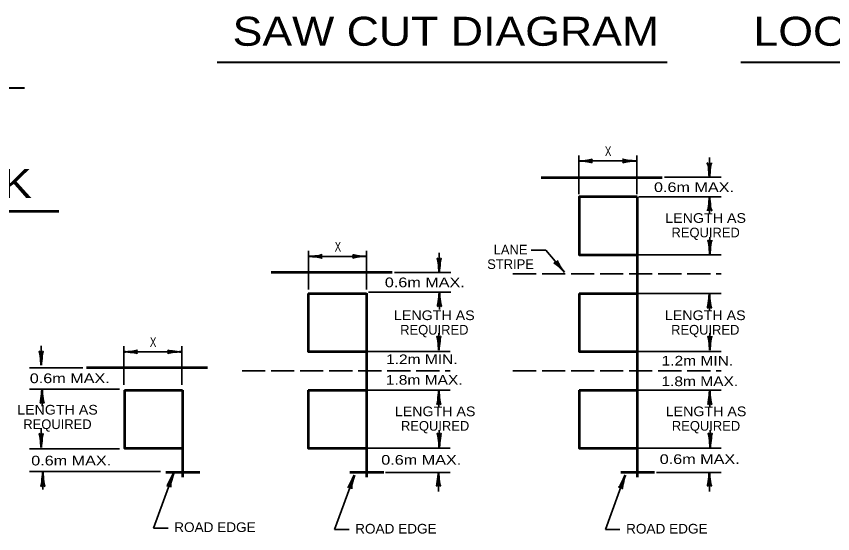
# Model space of a CAD drawing. Extents: x -90 to 623, y -379 to 75.
# Drawn here: x 208.1 to 376.8, y -182.3 to -75.3 of the extents above; entities that cross this region are included whole.
import ezdxf
from ezdxf.enums import TextEntityAlignment as Align

# ---------------------------------------------------------------- set-up
doc = ezdxf.new("R2010")
doc.units = 0
doc.header["$LTSCALE"] = 0.8
doc.linetypes.add('LONG_DASHED', pattern=[7.5, 6, -1.5])
doc.layers.add('1', color=7, linetype='Continuous', lineweight=35)

msp = doc.modelspace()

# ---------------------------------------------------------------- linework, layer by layer
at = {"layer": '1', "lineweight": 40}
for p, q in [((249.5781, -84.8174), (342.6167, -84.8174)), ((357.8467, -84.8174), (443.6682, -84.8174)), ((128.1151, -90.0752), (209.7699, -90.0752))]:
    msp.add_line(p, q, dxfattribs=at)
at = {"layer": '1'}
for p, q in [((324.3488, -112.0774), (324.3488, -104.0774)), ((336.3488, -112.0774), (336.3488, -104.0774)), ((351.3414, -108.4852), (351.3414, -104.4852)), ((324.2692, -105.2347), (336.2847, -105.2347)), ((342.092, -108.5765), (353.7611, -108.5765)), ((336.7611, -112.6343), (353.7611, -112.6343)), ((351.3812, -116.186), (351.3812, -112.686)), ((351.4209, -124.4781), (351.4209, -120.9781)), ((268.4928, -131.8101), (268.4928, -123.8101)), ((280.4928, -131.8101), (280.4928, -123.8101)), ((295.4853, -128.2178), (295.4853, -124.2178)), ((336.7611, -124.6343), (353.7611, -124.6343)), ((268.4132, -124.9674), (280.4287, -124.9674)), ((286.2359, -128.3092), (297.905, -128.3092)), ((280.905, -132.367), (297.905, -132.367)), ((295.5251, -135.9187), (295.5251, -132.4187)), ((336.7611, -132.6343), (353.7611, -132.6343)), ((351.3414, -136.2764), (351.3414, -132.7764)), ((295.4209, -144.3696), (295.4209, -140.8696)), ((351.4209, -144.3696), (351.4209, -140.8696)), ((213.2128, -147.4731), (213.2128, -143.4731)), ((230.221, -144.7001), (242.2365, -144.7001)), ((230.3006, -151.5427), (230.3006, -143.5427)), ((242.3006, -151.5427), (242.3006, -143.5427)), ((280.7611, -144.6343), (297.7611, -144.6343)), ((336.7611, -144.6343), (353.7611, -144.6343)), ((221.8063, -147.9942), (210.8156, -147.9942)), ((229.4447, -152.45), (210.8156, -152.45)), ((213.4117, -155.9697), (213.4117, -152.4697)), ((280.7611, -152.6343), (297.7611, -152.6343)), ((295.4209, -156.2476), (295.4209, -152.7476)), ((336.7611, -152.6343), (353.7611, -152.6343)), ((351.4209, -156.2476), (351.4209, -152.7476)), ((213.2128, -164.5004), (213.2128, -160.5004)), ((295.5005, -164.4203), (295.5005, -160.9203)), ((351.5005, -164.4203), (351.5005, -160.9203)), ((229.4447, -164.7682), (210.8156, -164.7682)), ((280.7611, -164.6343), (297.7611, -164.6343)), ((336.7611, -164.6343), (353.7611, -164.6343)), ((237.8789, -169.4774), (210.8156, -169.4774)), ((213.5708, -173.1562), (213.5708, -169.6562)), ((240.5595, -169.8673), (236.4582, -181.1357)), ((277.9561, -170.1856), (273.8548, -181.4539)), ((284.421, -169.6232), (297.7611, -169.6232)), ((295.3413, -173.6157), (295.3413, -169.6157)), ((333.9561, -170.1856), (329.8548, -181.4539)), ((340.421, -169.6232), (353.7611, -169.6232)), ((351.3413, -173.6157), (351.3413, -169.6157)), ((236.4582, -181.1357), (239.4582, -181.1357)), ((273.8548, -181.4539), (276.8548, -181.4539)), ((329.8548, -181.4539), (332.8548, -181.4539))]:
    msp.add_line(p, q, dxfattribs=at)
at = {"layer": '1', "lineweight": 53}
for p, q in [((316.5513, -108.6561), (341.5513, -108.6561)), ((336.4429, -112.6152), (336.4429, -170.6152)), ((0.8544, -115.6087), (216.8702, -115.6087)), ((260.7747, -128.2296), (285.7747, -128.2296)), ((268.4429, -132.6152), (280.4429, -132.6152)), ((280.4429, -132.5694), (280.4429, -170.6152)), ((280.4429, -132.649), (280.4429, -170.6152)), ((324.4429, -132.6152), (336.4429, -132.6152)), ((222.5826, -147.9622), (247.5826, -147.9622)), ((230.4429, -152.6152), (242.4429, -152.6152)), ((242.4429, -152.6152), (242.4429, -170.6152)), ((242.4429, -152.6292), (242.4429, -170.6152)), ((268.4429, -152.6152), (280.4429, -152.6152)), ((324.4429, -152.6152), (336.4429, -152.6152)), ((239.0214, -169.5842), (246.0214, -169.5842)), ((277.0214, -169.5842), (284.0214, -169.5842)), ((333.0214, -169.5842), (340.0214, -169.5842))]:
    msp.add_line(p, q, dxfattribs=at)
at = {"layer": '1', "linetype": 'LONG_DASHED'}
for p, q in [((310.7429, -128.6062), (353.7429, -128.6062)), ((254.7429, -148.6062), (297.7429, -148.6062)), ((310.7429, -148.6062), (353.7429, -148.6062))]:
    msp.add_line(p, q, dxfattribs=at)
at = {"layer": '1', "lineweight": 53}
for points in [[(336.4429, -112.6152), (324.4429, -112.6152), (324.4429, -124.6152), (336.4429, -124.6152)], [(268.4429, -132.6152), (268.4429, -144.6152), (280.4429, -144.6152)], [(324.4429, -132.6152), (324.4429, -144.6152), (336.4429, -144.6152)], [(230.4429, -152.6152), (230.4429, -164.6152), (242.4429, -164.6152)], [(268.4429, -152.6152), (268.4429, -164.6152), (280.4429, -164.6152)], [(324.4429, -152.6152), (324.4429, -164.6152), (336.4429, -164.6152)]]:
    msp.add_lwpolyline(points, dxfattribs=at)
at = {"layer": '1'}
msp.add_lwpolyline([(321.3846, -128.2541), (317.5278, -123.6578), (314.5278, -123.6578)], dxfattribs=at)
at = {"layer": '1', "lineweight": 40}
for centre, major_axis, ratio, start_param, end_param in [((325.3898, -105.4464), (1.7565, -0.1757), 0.07063, 6.28230741, 8.55970261), ((325.3604, -104.9585), (-1.7857, -0.1562), 0.122415, 0.89635335, 3.14159265), ((335.1936, -105.511), (1.7857, 0.1562), 0.122415, 0.89635335, 3.14159265), ((335.1936, -105.511), (1.7857, 0.1562), 0.122415, 0.89635335, 3.14159265), ((335.1642, -105.0231), (1.7565, -0.1757), 0.07063, 3.14071475, 5.41810995), ((335.1642, -105.0231), (1.7565, -0.1757), 0.07063, 3.14071475, 5.41810995), ((351.0651, -107.394), (0.1562, -1.7857), 0.122415, 0.89635335, 3.14159265), ((351.553, -107.3647), (0.1757, 1.7565), 0.07063, 6.28230741, 8.55970261), ((351.1696, -113.8065), (-0.1757, -1.7565), 0.07063, 6.28230741, 8.55970261), ((351.6575, -113.7772), (-0.1562, 1.7857), 0.122415, 0.89635335, 3.14159265), ((351.1446, -123.3869), (0.1562, -1.7857), 0.122415, 0.89635335, 3.14159265), ((351.6325, -123.3576), (0.1757, 1.7565), 0.07063, 6.28230741, 8.55970261), ((269.5044, -124.6911), (-1.7857, -0.1562), 0.122415, 0.89635335, 3.14159265), ((279.3082, -124.7558), (1.7565, -0.1757), 0.07063, 3.14071475, 5.41810995), ((279.3082, -124.7558), (1.7565, -0.1757), 0.07063, 3.14071475, 5.41810995), ((269.5337, -125.179), (1.7565, -0.1757), 0.07063, 6.28230741, 8.55970261), ((279.3375, -125.2437), (1.7857, 0.1562), 0.122415, 0.89635335, 3.14159265), ((279.3375, -125.2437), (1.7857, 0.1562), 0.122415, 0.89635335, 3.14159265), ((295.209, -127.1266), (0.1562, -1.7857), 0.122415, 0.89635335, 3.14159265), ((295.6969, -127.0973), (0.1757, 1.7565), 0.07063, 6.28230741, 8.55970261), ((320.4715, -127.5958), (1.2674, -1.2675), 0.122415, 0.89635335, 3.14159265), ((320.8264, -127.2597), (0.9945, -1.4584), 0.07063, 3.14071475, 5.41810995), ((295.3135, -133.5392), (-0.1757, -1.7565), 0.07063, 6.28230741, 8.55970261), ((295.8014, -133.5099), (-0.1562, 1.7857), 0.122415, 0.89635335, 3.14159265), ((351.1298, -133.8969), (-0.1757, -1.7565), 0.07063, 6.28230741, 8.55970261), ((351.6177, -133.8676), (-0.1562, 1.7857), 0.122415, 0.89635335, 3.14159265), ((295.1446, -143.2784), (0.1562, -1.7857), 0.122415, 0.89635335, 3.14159265), ((295.6325, -143.2491), (0.1757, 1.7565), 0.07063, 6.28230741, 8.55970261), ((351.1446, -143.2784), (0.1562, -1.7857), 0.122415, 0.89635335, 3.14159265), ((351.6325, -143.2491), (0.1757, 1.7565), 0.07063, 6.28230741, 8.55970261), ((212.9365, -146.3819), (0.1562, -1.7857), 0.122415, 0.89635335, 3.14159265), ((213.4244, -146.3526), (0.1757, 1.7565), 0.07063, 6.28230741, 8.55970261), ((231.3415, -144.9117), (1.7565, -0.1757), 0.07063, 6.28230741, 8.55970261), ((231.3122, -144.4238), (-1.7857, -0.1562), 0.122415, 0.89635335, 3.14159265), ((241.1453, -144.9764), (1.7857, 0.1562), 0.122415, 0.89635335, 3.14159265), ((241.116, -144.4885), (1.7565, -0.1757), 0.07063, 3.14071475, 5.41810995), ((213.2001, -153.5902), (-0.1757, -1.7565), 0.07063, 6.28230741, 8.55970261), ((213.688, -153.5609), (-0.1562, 1.7857), 0.122415, 0.89635335, 3.14159265), ((295.2093, -153.8681), (-0.1757, -1.7565), 0.07063, 6.28230741, 8.55970261), ((295.6972, -153.8388), (-0.1562, 1.7857), 0.122415, 0.89635335, 3.14159265), ((351.2093, -153.8681), (-0.1757, -1.7565), 0.07063, 6.28230741, 8.55970261), ((351.6972, -153.8388), (-0.1562, 1.7857), 0.122415, 0.89635335, 3.14159265), ((212.9365, -163.4092), (0.1562, -1.7857), 0.122415, 0.89635335, 3.14159265), ((213.4244, -163.3799), (0.1757, 1.7565), 0.07063, 6.28230741, 8.55970261), ((295.2242, -163.3291), (0.1562, -1.7857), 0.122415, 0.89635335, 3.14159265), ((295.7121, -163.2998), (0.1757, 1.7565), 0.07063, 6.28230741, 8.55970261), ((351.2242, -163.3291), (0.1562, -1.7857), 0.122415, 0.89635335, 3.14159265), ((351.7121, -163.2998), (0.1757, 1.7565), 0.07063, 6.28230741, 8.55970261), ((213.3592, -170.7767), (-0.1757, -1.7565), 0.07063, 6.28230741, 8.55970261), ((213.8471, -170.7474), (-0.1562, 1.7857), 0.122415, 0.89635335, 3.14159265), ((239.9774, -170.8479), (0.7658, 1.5905), 0.07063, 3.14071475, 5.41810995), ((240.4459, -170.9872), (0.464, 1.7314), 0.122415, 0.89635335, 3.14159265), ((277.374, -171.1661), (0.7658, 1.5905), 0.07063, 3.14071475, 5.41810995), ((277.8425, -171.3055), (0.464, 1.7314), 0.122415, 0.89635335, 3.14159265), ((295.1297, -170.7362), (-0.1757, -1.7565), 0.07063, 6.28230741, 8.55970261), ((295.6176, -170.7069), (-0.1562, 1.7857), 0.122415, 0.89635335, 3.14159265), ((333.374, -171.1661), (0.7658, 1.5905), 0.07063, 3.14071475, 5.41810995), ((333.8425, -171.3055), (0.464, 1.7314), 0.122415, 0.89635335, 3.14159265), ((351.1297, -170.7362), (-0.1757, -1.7565), 0.07063, 6.28230741, 8.55970261), ((351.6176, -170.7069), (-0.1562, 1.7857), 0.122415, 0.89635335, 3.14159265)]:
    msp.add_ellipse(centre, major_axis=major_axis, ratio=ratio, start_param=start_param, end_param=end_param, dxfattribs=at)

# ---------------------------------------------------------------- texts
at = {"layer": '1'}
for s, height, width, p in [('SAW CUT DIAGRAM', 6, 1.15, (252.786, -81.409)), ('LOOP WIRE PLAN', 6, 1.15, (360.4532, -81.409)), ('X', 2, 0.75, (329.7391, -104.2271)), ('TYPICAL SECTION IN GUTTER AND SIDEWALK', 6, 1.15, (4.6777, -112.8777)), ('0.6m MAX.', 2, 1.25, (339.8897, -111.6557)), ('X', 2, 0.75, (273.883, -123.9597)), ('0.6m MAX.', 2, 1.25, (284.2554, -131.3397)), ('X', 2, 0.75, (235.6908, -143.6924)), ('1.2m MIN.', 2, 1.2, (284.4996, -147.2422)), ('1.2m MIN.', 2, 1.2, (341.4655, -147.5382)), ('0.6m MAX.', 2, 1.25, (210.8655, -151.1716)), ('1.8m MAX.', 2, 1.2, (284.4597, -151.499)), ('1.8m MAX.', 2, 1.2, (341.4256, -151.795)), ('0.6m MAX.', 2, 1.25, (211.1614, -168.1916)), ('0.6m MAX.', 2, 1.25, (283.5156, -168.0436)), ('0.6m MAX.', 2, 1.25, (341.0734, -167.8956)), ('ROAD EDGE', 2, 1.05, (240.7186, -181.9615)), ('ROAD EDGE', 2, 1.05, (278.1152, -182.2798)), ('ROAD EDGE', 2, 1.05, (334.1152, -182.2798))]:
    msp.add_text(s, height=height, dxfattribs=dict(at, width=width)).set_placement(p)
at = {"layer": '1', "width": 1.1}
for p in [(350.5656, -118.0289), (294.486, -138.1393), (350.486, -138.1393), (216.5897, -157.673), (294.6451, -158.0111), (350.6451, -158.0111)]:
    msp.add_text('LENGTH AS', height=2, dxfattribs=at).set_placement(p, align=Align.CENTER)
at = {"layer": '1'}
for s, p in [('REQUIRED', (350.5656, -121.0289)), ('LANE', (310.2452, -124.5714)), ('STRIPE', (310.2452, -127.5714)), ('REQUIRED', (294.486, -141.1393)), ('REQUIRED', (350.486, -141.1393)), ('REQUIRED', (216.5897, -160.673)), ('REQUIRED', (294.6451, -161.0111)), ('REQUIRED', (350.6451, -161.0111))]:
    msp.add_text(s, height=2, dxfattribs=at).set_placement(p, align=Align.CENTER)

doc.saveas('drawing.dxf')
